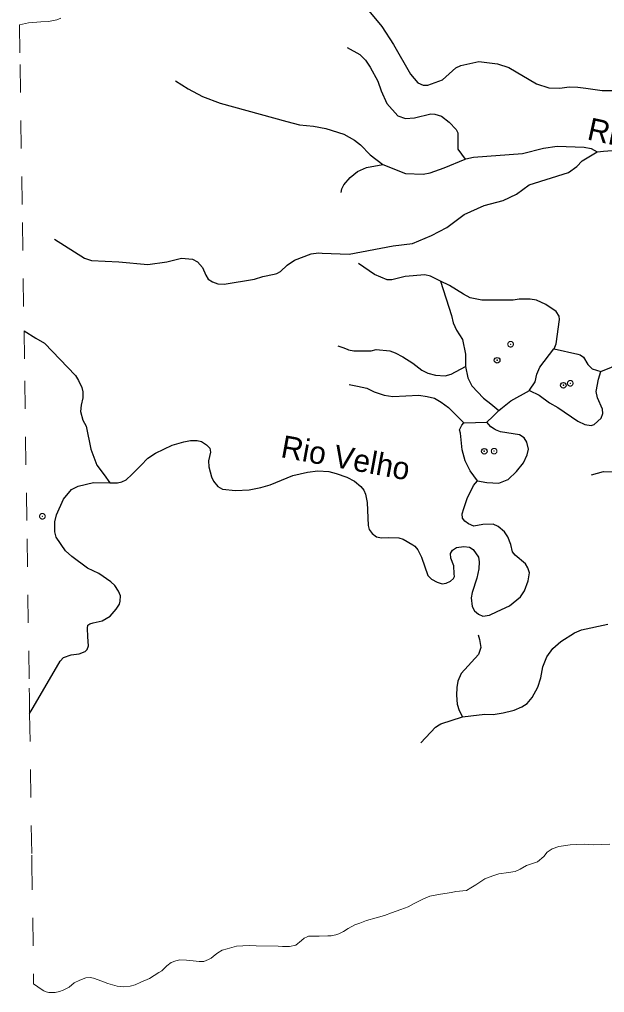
# Model space of a CAD drawing. Extents: x 267.7 to 296, y 7537.7 to 7565.8.
# Drawn here: x 267.848 to 269.938, y 7551.945 to 7555.422 of the extents above; entities that cross this region are included whole.
import ezdxf
from ezdxf.enums import TextEntityAlignment as Align

# ---------------------------------------------------------------- set-up
doc = ezdxf.new("R2010")
doc.units = 0
doc.header["$LTSCALE"] = 0.04
doc.header["$PDMODE"] = 32
doc.header["$PDSIZE"] = 0.02
doc.linetypes.add('SHORT_DASHED', pattern=[2.7, 1.5, -1.2])
for name, color, linetype, lineweight in [('21', 7, 'SHORT_DASHED', 13), ('62', 7, 'SHORT_DASHED', 13), ('7', 7, 'Continuous', 25)]:
    doc.layers.add(name, color=color, linetype=linetype, lineweight=lineweight)
doc.layers.add('54', color=7, linetype='Continuous')
doc.layers.add('61', color=7, linetype='Continuous')

msp = doc.modelspace()

# ---------------------------------------------------------------- linework, layer by layer
at = {"layer": '21'}
for points in [[(267.8481, 7555.4034), (267.8808, 7555.4102), (267.9249, 7555.4139), (267.9516, 7555.4158), (267.9815, 7555.4208), (267.9964, 7555.427)], [(269.9566, 7552.4753), (269.8967, 7552.4731), (269.8664, 7552.4753), (269.839, 7552.4746), (269.8152, 7552.4731), (269.7914, 7552.4688), (269.774, 7552.4667), (269.751, 7552.4587), (269.7329, 7552.4472), (269.7214, 7552.4313), (269.6983, 7552.4118), (269.6593, 7552.3995), (269.6362, 7552.3858), (269.6189, 7552.3779), (269.5944, 7552.3736), (269.5597, 7552.3692), (269.5381, 7552.362), (269.5107, 7552.3519), (269.4782, 7552.3296), (269.4602, 7552.3195), (269.445, 7552.3094), (269.4068, 7552.3057), (269.3916, 7552.3029), (269.3512, 7552.2964), (269.3137, 7552.2891), (269.2884, 7552.2783), (269.2552, 7552.2617), (269.2358, 7552.2516), (269.2098, 7552.2415), (269.1766, 7552.2293), (269.1513, 7552.2206), (269.1217, 7552.2119), (269.0878, 7552.2026), (269.0633, 7552.1932), (269.046, 7552.1867), (269.0222, 7552.1737), (269.0056, 7552.1636), (268.989, 7552.1549), (268.9774, 7552.1513), (268.9616, 7552.1477), (268.9493, 7552.1477), (268.9183, 7552.147), (268.8807, 7552.1463), (268.875, 7552.1441), (268.8649, 7552.1398), (268.8548, 7552.1311), (268.8346, 7552.1145), (268.8129, 7552.1095), (268.7877, 7552.1095), (268.7718, 7552.1102), (268.6939, 7552.1124), (268.6679, 7552.1131), (268.6231, 7552.1102), (268.59, 7552.1015), (268.5726, 7552.0965), (268.556, 7552.0864), (268.5474, 7552.0792), (268.5329, 7552.0676), (268.5228, 7552.0626), (268.5062, 7552.0561), (268.4897, 7552.0561), (268.468, 7552.0582), (268.4449, 7552.0604), (268.4204, 7552.0619), (268.406, 7552.0582), (268.3901, 7552.0525), (268.3749, 7552.0402), (268.3562, 7552.0229), (268.3453, 7552.0164), (268.3121, 7551.9947), (268.2811, 7551.9818), (268.2616, 7551.9724), (268.2436, 7551.9681), (268.2183, 7551.9652), (268.1974, 7551.9681), (268.1635, 7551.9774), (268.1426, 7551.9861), (268.1123, 7551.9969), (268.1007, 7551.9991), (268.0856, 7551.9976), (268.0639, 7551.9897), (268.0437, 7551.9796), (268.025, 7551.9637), (268.004, 7551.9536), (267.991, 7551.9493), (267.9752, 7551.9457)], [(267.9261, 7551.9565), (267.9131, 7551.9659), (267.8987, 7551.9767)], [(267.9752, 7551.9457), (267.9535, 7551.945), (267.9434, 7551.9471), (267.9348, 7551.9515), (267.9261, 7551.9565)]]:
    msp.add_lwpolyline(points, dxfattribs=at)
for p in [(269.6021, 7554.2619), (269.8152, 7554.1223), (269.5433, 7553.8798), (267.93, 7553.6469)]:
    msp.add_point(p, dxfattribs=at)
at = {"layer": '54'}
for p in [(269.5539, 7554.2046), (269.7905, 7554.1151), (269.5083, 7553.8794)]:
    msp.add_point(p, dxfattribs=at)
at = {"layer": '62'}
for points in [[(267.8481, 7555.4034), (267.8502, 7555.2614), (267.8586, 7554.6964), (267.8643, 7554.3101)], [(267.8643, 7554.3101), (267.8669, 7554.1313), (267.8753, 7553.5663), (267.8831, 7553.0327), (267.8836, 7553.0012), (267.8845, 7552.9418)], [(267.8845, 7552.9418), (267.892, 7552.4361), (267.8924, 7552.4122), (267.8987, 7551.9767)]]:
    msp.add_lwpolyline(points, dxfattribs=at)
at = {"layer": '7'}
for points in [[(269.0895, 7555.461), (269.142, 7555.3976), (269.184, 7555.3336), (269.2449, 7555.2265), (269.2712, 7555.196), (269.2894, 7555.1881), (269.3067, 7555.1875), (269.3594, 7555.2067), (269.4067, 7555.2491), (269.4247, 7555.2582), (269.4888, 7555.2722), (269.5555, 7555.2641), (269.5953, 7555.2507), (269.6949, 7555.1921), (269.7391, 7555.1786), (269.7782, 7555.1768), (269.8119, 7555.1818), (269.8427, 7555.181), (269.8706, 7555.1771), (269.9288, 7555.1688), (269.9687, 7555.1689)], [(269.0186, 7555.3218), (269.0637, 7555.2971), (269.0834, 7555.2775), (269.1009, 7555.2519), (269.1277, 7555.2018), (269.1397, 7555.1669), (269.1602, 7555.1224), (269.1998, 7555.0775), (269.2266, 7555.0691), (269.2586, 7555.0704), (269.3177, 7555.0855), (269.3314, 7555.0842), (269.3548, 7555.0764), (269.3832, 7555.0554), (269.4076, 7555.0296), (269.414, 7555.0174), (269.4139, 7554.9594), (269.4401, 7554.9237)], [(268.4055, 7555.2033), (268.451, 7555.1745), (268.5022, 7555.1475), (268.5643, 7555.1228), (268.8028, 7555.0584), (268.8485, 7555.0461), (268.8982, 7555.0415), (268.9424, 7555.0333), (269.0068, 7555.0122), (269.0448, 7554.9911), (269.0662, 7554.9749), (269.1009, 7554.9392), (269.1453, 7554.9039)], [(267.9727, 7554.6376), (268.0809, 7554.57), (268.1053, 7554.5608), (268.2026, 7554.5562), (268.3068, 7554.5469), (268.3748, 7554.5558), (268.427, 7554.569), (268.4661, 7554.5664), (268.4842, 7554.5569), (268.5014, 7554.5361), (268.5136, 7554.5089), (268.5226, 7554.4944), (268.5369, 7554.4852), (268.5562, 7554.4778), (268.579, 7554.4764), (268.6874, 7554.4938), (268.7176, 7554.5039), (268.7578, 7554.5118), (268.7668, 7554.515), (268.7809, 7554.5223), (268.8036, 7554.5441), (268.8307, 7554.5623), (268.8894, 7554.5849), (268.9159, 7554.5884), (268.9291, 7554.5878), (269.0254, 7554.5836), (269.1829, 7554.6141), (269.2517, 7554.6213), (269.3202, 7554.65), (269.3741, 7554.6795), (269.4361, 7554.7253), (269.5076, 7554.7573), (269.5758, 7554.7758), (269.6229, 7554.7987), (269.6684, 7554.8312), (269.8087, 7554.8755), (269.8386, 7554.8972), (269.8573, 7554.9174), (269.9114, 7554.9497)], [(269.4401, 7554.9237), (269.4427, 7554.9248), (269.4698, 7554.9308), (269.6452, 7554.9437), (269.72, 7554.963), (269.7688, 7554.9696), (269.8644, 7554.9658), (269.8901, 7554.9611), (269.9114, 7554.9497)], [(269.9114, 7554.9497), (269.9121, 7554.9493), (269.9345, 7554.9514), (269.9953, 7554.9571)], [(268.9971, 7554.8042), (268.9991, 7554.8173), (269.0068, 7554.832), (269.0297, 7554.858), (269.0557, 7554.8788), (269.0874, 7554.893), (269.1453, 7554.9039)], [(269.1453, 7554.9039), (269.1456, 7554.9037), (269.2262, 7554.8725), (269.2903, 7554.8692), (269.3143, 7554.874), (269.3651, 7554.8919), (269.4401, 7554.9237)], [(269.3516, 7554.4877), (269.3156, 7554.5057), (269.2953, 7554.5103), (269.2258, 7554.5044), (269.1782, 7554.492), (269.1611, 7554.4919), (269.1157, 7554.5106), (269.0588, 7554.5505)], [(269.3516, 7554.4877), (269.3915, 7554.3645), (269.3972, 7554.3386), (269.4084, 7554.3127), (269.4305, 7554.2793), (269.4407, 7554.2262), (269.4406, 7554.1863), (269.4415, 7554.1817)], [(269.7572, 7554.2457), (269.7645, 7554.2632), (269.7773, 7554.3508), (269.7758, 7554.3619), (269.7646, 7554.3788), (269.7275, 7554.4043), (269.6942, 7554.419), (269.6725, 7554.4231), (269.6333, 7554.4225), (269.6113, 7554.4189), (269.4994, 7554.4196), (269.4573, 7554.4272), (269.4343, 7554.4411), (269.3842, 7554.4714), (269.3516, 7554.4877)], [(267.8643, 7554.3101), (267.9067, 7554.284), (267.9372, 7554.2653), (268.0484, 7554.1506), (268.0595, 7554.1326), (268.0712, 7554.1077), (268.0746, 7554.0912), (268.074, 7554.0705), (268.0679, 7554.0438), (268.0658, 7554.0213), (268.0741, 7553.9905), (268.0859, 7553.9691), (268.1031, 7553.8865), (268.1247, 7553.8296), (268.15, 7553.7954), (268.1707, 7553.767)], [(268.9851, 7554.2564), (269.0066, 7554.2493), (269.0205, 7554.2432), (269.0234, 7554.2419), (269.0419, 7554.2378), (269.1038, 7554.2378), (269.1226, 7554.2425), (269.1705, 7554.2381), (269.19, 7554.2312), (269.2177, 7554.2174), (269.2534, 7554.1947), (269.2856, 7554.1693), (269.3061, 7554.1581), (269.3341, 7554.1512), (269.3683, 7554.1489), (269.3895, 7554.1543), (269.4415, 7554.1817)], [(269.6691, 7554.0971), (269.6697, 7554.0974), (269.6902, 7554.127), (269.6963, 7554.1549), (269.706, 7554.1795), (269.7571, 7554.2455), (269.7572, 7554.2457)], [(269.7572, 7554.2457), (269.8423, 7554.2262), (269.8511, 7554.2236), (269.863, 7554.2155), (269.8781, 7554.1895), (269.8932, 7554.1743), (269.9092, 7554.1691), (269.9246, 7554.165)], [(269.4415, 7554.1817), (269.4495, 7554.1413), (269.4639, 7554.1134), (269.5056, 7554.0695), (269.5313, 7554.049), (269.5607, 7554.0255)], [(269.9246, 7554.165), (269.9626, 7554.1803), (270.0118, 7554.2016)], [(269.6691, 7554.0971), (269.7046, 7554.0795), (269.7406, 7554.0525), (269.7706, 7554.0361), (269.8424, 7553.9871), (269.8678, 7553.9755), (269.8899, 7553.9717), (269.9001, 7553.9754), (269.9251, 7553.9972), (269.9311, 7554.0146), (269.9306, 7554.0299), (269.913, 7554.0699), (269.9083, 7554.0933), (269.9156, 7554.1371), (269.9246, 7554.165)], [(269.025, 7554.1183), (269.0554, 7554.1116), (269.0885, 7554.1043), (269.1146, 7554.0913), (269.1501, 7554.08), (269.182, 7554.0755), (269.2749, 7554.0794), (269.3044, 7554.0753), (269.3303, 7554.0695), (269.3545, 7554.0543), (269.3806, 7554.0356), (269.4357, 7553.9807)], [(269.5607, 7554.0255), (269.5669, 7554.0315), (269.6025, 7554.0595), (269.6691, 7554.0971)], [(269.5171, 7553.9832), (269.5382, 7554.0037), (269.5607, 7554.0255)], [(269.4838, 7553.7737), (269.4581, 7553.809), (269.4402, 7553.8453), (269.4291, 7553.8848), (269.4236, 7553.9445), (269.4197, 7553.9565), (269.4276, 7553.973), (269.4357, 7553.9807)], [(269.4357, 7553.9807), (269.4364, 7553.9813), (269.5171, 7553.9832)], [(269.4838, 7553.7737), (269.5174, 7553.7676), (269.5607, 7553.7649), (269.5904, 7553.7774), (269.5936, 7553.7787), (269.6237, 7553.8066), (269.6484, 7553.8384), (269.6618, 7553.8671), (269.6655, 7553.887), (269.6607, 7553.912), (269.6503, 7553.9279), (269.6341, 7553.9378), (269.566, 7553.9489), (269.5483, 7553.9558), (269.5442, 7553.9585), (269.5315, 7553.9671), (269.5171, 7553.9832)], [(268.1707, 7553.767), (268.1982, 7553.7669), (268.2141, 7553.7699), (268.229, 7553.777), (268.2495, 7553.7965), (268.2811, 7553.8289), (268.307, 7553.855), (268.3345, 7553.8724), (268.3931, 7553.9009), (268.4348, 7553.9136), (268.4589, 7553.9176), (268.4825, 7553.9176), (268.4979, 7553.9145), (268.5166, 7553.902), (268.5277, 7553.8909), (268.5308, 7553.8765), (268.5267, 7553.8611), (268.5236, 7553.8457), (268.5246, 7553.8242), (268.5338, 7553.7883), (268.541, 7553.7729), (268.5569, 7553.7537), (268.5729, 7553.7445), (268.6196, 7553.7391), (268.669, 7553.7416), (268.7104, 7553.7503), (268.7431, 7553.7591), (268.8249, 7553.7925), (268.8765, 7553.8052), (268.9141, 7553.8091), (268.9526, 7553.8067), (268.9793, 7553.7995), (269.0173, 7553.7872), (269.045, 7553.7729), (269.0671, 7553.7532), (269.0778, 7553.74), (269.084, 7553.7256), (269.09, 7553.6962), (269.0936, 7553.6137), (269.0973, 7553.5994), (269.1076, 7553.585), (269.123, 7553.5737), (269.1405, 7553.5696), (269.1671, 7553.5707), (269.2029, 7553.5695), (269.2182, 7553.5655), (269.2529, 7553.5446), (269.2605, 7553.54), (269.2708, 7553.5271), (269.284, 7553.5003), (269.3063, 7553.4356), (269.3201, 7553.4218), (269.3396, 7553.4116), (269.3581, 7553.4054), (269.3724, 7553.4075), (269.3878, 7553.4157), (269.3981, 7553.4249), (269.4022, 7553.4321), (269.4008, 7553.4417), (269.3991, 7553.4701), (269.3889, 7553.4968), (269.3878, 7553.5142), (269.395, 7553.5255), (269.4084, 7553.5358), (269.4348, 7553.5395), (269.4556, 7553.5368), (269.4687, 7553.5277), (269.4873, 7553.5003), (269.4901, 7553.4846), (269.489, 7553.4588), (269.4818, 7553.4259), (269.4643, 7553.375), (269.4615, 7553.3552), (269.4647, 7553.3245), (269.473, 7553.3089), (269.4874, 7553.2976), (269.5032, 7553.2902), (269.5267, 7553.2942), (269.5538, 7553.3066), (269.5981, 7553.327), (269.6372, 7553.3592), (269.6518, 7553.3808), (269.6649, 7553.4162), (269.6693, 7553.4449), (269.6639, 7553.4629), (269.6549, 7553.4767), (269.6184, 7553.5077), (269.6085, 7553.5202), (269.6029, 7553.5467), (269.5921, 7553.5737), (269.58, 7553.5919), (269.5576, 7553.6105), (269.5395, 7553.6187), (269.5034, 7553.6174), (269.471, 7553.6122)], [(269.8907, 7553.7956), (269.9336, 7553.8068), (269.9663, 7553.8056), (269.9908, 7553.7966), (270.0404, 7553.7784), (270.1232, 7553.7411), (270.1481, 7553.7364), (270.1804, 7553.7353), (270.213, 7553.7272), (270.2511, 7553.7026)], [(267.8845, 7552.9418), (267.8903, 7552.9518), (267.8975, 7552.9642), (267.994, 7553.1295), (268.0048, 7553.1428), (268.0326, 7553.1514), (268.0617, 7553.1559), (268.0833, 7553.1642), (268.0904, 7553.1714), (268.0945, 7553.1837), (268.0921, 7553.2156), (268.0905, 7553.2474), (268.0925, 7553.2576), (268.0997, 7553.2627), (268.1111, 7553.2665), (268.1434, 7553.2729), (268.1715, 7553.2904), (268.1935, 7553.3147), (268.2054, 7553.3325), (268.2074, 7553.3438), (268.2085, 7553.3623), (268.2018, 7553.3794), (268.1891, 7553.4), (268.1746, 7553.4124), (268.131, 7553.4425), (268.0916, 7553.461), (268.0356, 7553.5027), (268.0125, 7553.5237), (267.9786, 7553.5728), (267.9748, 7553.591), (267.9744, 7553.6275), (267.98, 7553.6526), (268.0052, 7553.7086), (268.0343, 7553.7422), (268.0579, 7553.7549), (268.1127, 7553.7673), (268.1707, 7553.767)], [(269.471, 7553.6122), (269.4515, 7553.6199), (269.4381, 7553.6292), (269.4309, 7553.6405), (269.4289, 7553.6559), (269.435, 7553.6754), (269.4475, 7553.7101), (269.4697, 7553.7576), (269.4838, 7553.7737)], [(269.4299, 7552.9302), (269.4597, 7552.9343), (269.5098, 7552.9394), (269.5396, 7552.9388), (269.5751, 7552.945), (269.6106, 7552.9528), (269.615, 7552.9546), (269.6425, 7552.9659), (269.6609, 7552.9782), (269.6786, 7552.999), (269.6991, 7553.036), (269.7104, 7553.0698), (269.7169, 7553.1089), (269.7317, 7553.1445), (269.7534, 7553.1745), (269.7817, 7553.1993), (269.8307, 7553.2303), (269.8558, 7553.2411), (269.95, 7553.2618)], [(269.4865, 7553.2228), (269.4915, 7553.2063), (269.4956, 7553.1775), (269.4874, 7553.1534), (269.4257, 7553.0851), (269.414, 7553.0579), (269.41, 7553.0355), (269.4084, 7553.0082), (269.4111, 7552.9753), (269.4186, 7552.9528), (269.4299, 7552.9302)], [(269.2813, 7552.8376), (269.3342, 7552.8937), (269.3466, 7552.9014), (269.3529, 7552.9053), (269.4299, 7552.9302)]]:
    msp.add_lwpolyline(points, dxfattribs=at)

# ---------------------------------------------------------------- texts
at = {"layer": '61'}
for s, rotation, p in [('Rio Barro Vermelho', 347.672, (270.3308, 7554.8942)), ('Rio Velho', 349.587, (269.006, 7553.8169))]:
    msp.add_text(s, height=0.08, rotation=rotation, dxfattribs=at).set_placement(p, align=Align.CENTER)

doc.saveas('drawing.dxf')
